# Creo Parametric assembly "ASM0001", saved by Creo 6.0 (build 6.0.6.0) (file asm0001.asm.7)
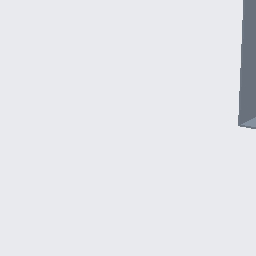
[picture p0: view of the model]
Units: Inch lbm Second (Pro/E Default); INCH, POUND, SECS

Created from: INLBS_ASM_DESIGN.ASM

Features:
  1. datum plane "ASM_RIGHT"
  2. datum plane "ASM_TOP"
  3. datum plane "ASM_FRONT"
  4. coordinate system
  5. component "PRT0001"
  6. component "LEFT"
  7. coordinate system
  8. component "BACK"
  9. component "PRT0002"
  10. component "RIGHT"

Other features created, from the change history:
  component "BACK.PRT"
  component "RIGHT.PRT"
  component "PRT0002.PRT"

Other named items: ACS4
